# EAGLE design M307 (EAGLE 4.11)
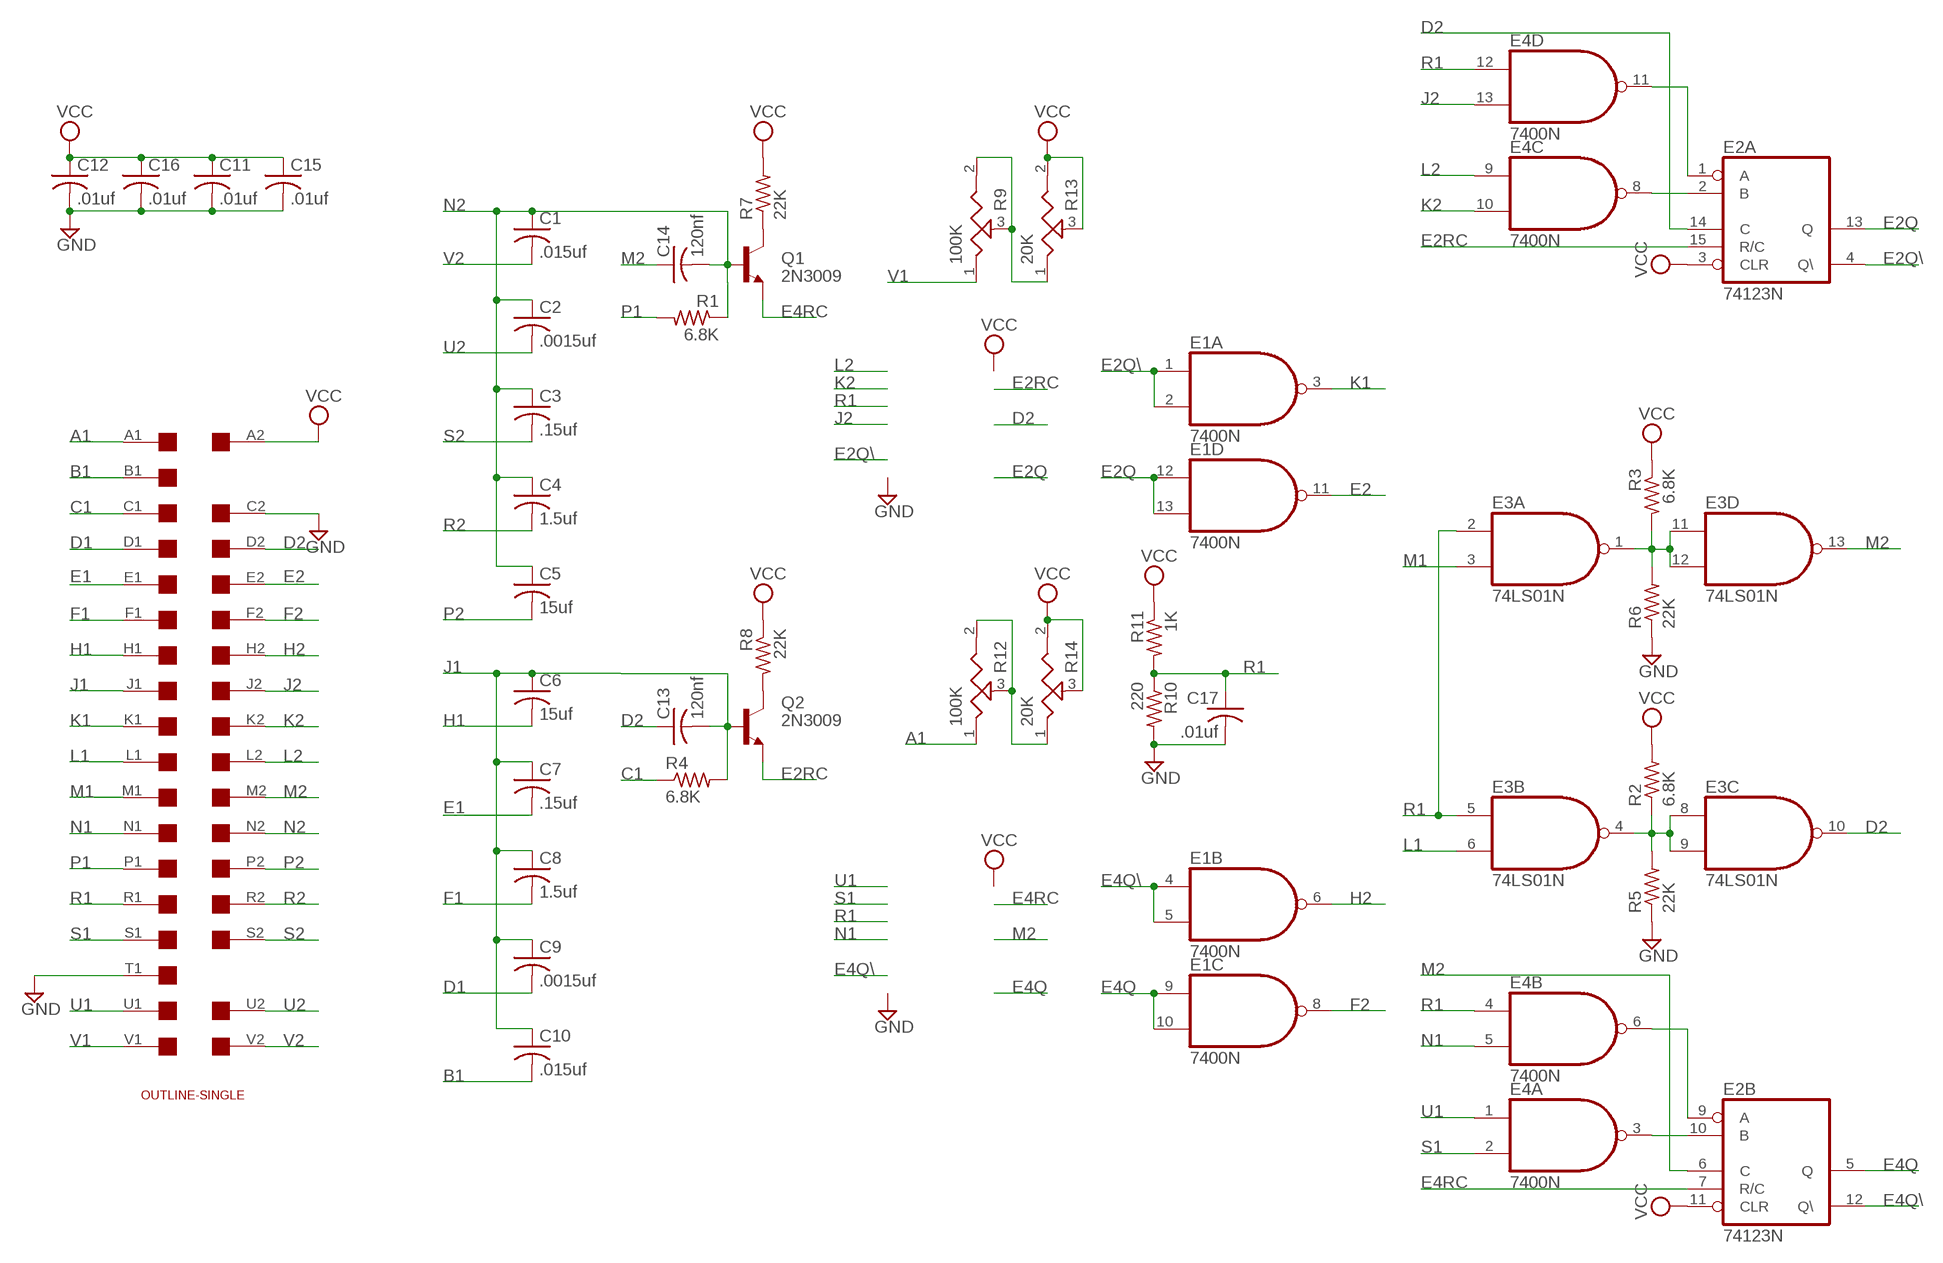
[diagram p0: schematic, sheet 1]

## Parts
C1  .015uf  C-US150-054X183  [C150-054X183]
C2  .0015uf  C-US050-025X075  [C050-025X075]
C3  .15uf  C-US102-043X133  [C102-043X133]
C4  1.5uf  C-US150-054X183  [C150-054X183]
C5  15uf  C-US150-054X183  [C150-054X183]
C6  15uf  C-US150-054X183  [C150-054X183]
C7  .15uf  C-US102-043X133  [C102-043X133]
C8  1.5uf  C-US150-054X183  [C150-054X183]
C9  .0015uf  C-US050-025X075  [C050-025X075]
C10  .015uf  C-US150-054X183  [C150-054X183]
C11  .01uf  C-US050-025X075  [C050-025X075]
C12  .01uf  C-US050-025X075  [C050-025X075]
C13  120nf  C-US075-032X103  [C075-032X103]
C14  120nf  C-US075-032X103  [C075-032X103]
C15  .01uf  C-US050-025X075  [C050-025X075]
C16  .01uf  C-US050-025X075  [C050-025X075]
C17  .01uf  C-US050-025X075  [C050-025X075]
E1  7400N  [DIL14]
E2  74123N  [DIL16]
E3  74LS01N  [DIL14]
E4  7400N  [DIL14]
Q1  2N3009  2N3019-NPN-TO39-EBC  [TO39]
Q2  2N3009  2N3019-NPN-TO39-EBC  [TO39]
R1  6.8K  R-US_0207/10  [0207/10]
R2  6.8K  R-US_0207/10  [0207/10]
R3  6.8K  R-US_0207/10  [0207/10]
R4  6.8K  R-US_0207/10  [0207/10]
R5  22K  R-US_0207/10  [0207/10]
R6  22K  R-US_0207/10  [0207/10]
R7  22K  R-US_0207/10  [0207/10]
R8  22K  R-US_0207/10  [0207/10]
R9  100K  POTUS-TRIM  [PT-SPIN]
R10  220  R-US_0207/10  [0207/10]
R11  1K  R-US_0207/10  [0207/10]
R12  100K  POTUS-TRIM  [PT-SPIN]
R13  20K  POTUS-TRIM  [PT-SPIN]
R14  20K  POTUS-TRIM  [PT-SPIN]
U$1  SINGLE  [EDGE-CON2]
U$4  OUTLINE-SINGLE  [SINGLE]

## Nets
A1: R12.1 U$1.A1
B1: C10.2 U$1.B1
C1: R4.1 U$1.C1
D1: C9.2 U$1.D1
D2: C13.1 E2.14(A:C) E3.10(C:O) U$1.D2
E1: C7.2 U$1.E1
E2: E1.11(D:O) U$1.E2
E2Q: E1.12(D:I0) E1.13(D:I1) E2.13(A:Q)
E2Q\: E1.1(A:I0) E1.2(A:I1) E2.4(A:Q\)
E2RC: E2.15(A:R/C) Q2.1(E)
E4Q: E1.9(C:I0) E1.10(C:I1) E2.5(B:Q)
E4Q\: E1.4(B:I0) E1.5(B:I1) E2.12(B:Q\)
E4RC: E2.7(B:R/C) Q1.1(E)
F1: C8.2 U$1.F1
F2: E1.8(C:O) U$1.F2
GND [power]: C11.2 C12.2 C15.2 C16.2 C17.2 R5.1 R6.1 R10.2 U$1.C2 U$1.T1
H1: C6.2 U$1.H1
H2: E1.6(B:O) U$1.H2
J1: C6.1 C7.1 C8.1 C9.1 C10.1 C13.2 Q2.2(B) R4.2 U$1.J1
J2: E4.13(D:I1) U$1.J2
K1: E1.3(A:O) U$1.K1
K2: E4.10(C:I1) U$1.K2
L1: E3.6(B:I1) U$1.L1
L2: E4.9(C:I0) U$1.L2
M1: E3.3(A:I1) U$1.M1
M2: C14.1 E2.6(B:C) E3.13(D:O) U$1.M2
N1: E4.5(B:I1) U$1.N1
N2: C1.1 C2.1 C3.1 C4.1 C5.1 C14.2 Q1.2(B) R1.1 U$1.N2
N$1: Q1.3(C) R7.1
N$2: E3.4(B:O) E3.8(C:I0) E3.9(C:I1) R2.1 R5.2
N$3: Q2.3(C) R8.2
N$4: E2.10(B:B) E4.3(A:O)
N$5: E3.1(A:O) E3.11(D:I0) E3.12(D:I1) R3.2 R6.2
N$6: E2.9(B:A) E4.6(B:O)
N$7: E2.1(A:A) E4.11(D:O)
N$8: E2.2(A:B) E4.8(C:O)
N$9 [power]: R9.2 R9.3 R13.1
N$10 [power]: R12.2 R12.3 R14.1
P1: R1.2 U$1.P1
P2: C5.2 U$1.P2
R1: C17.1 E3.2(A:I0) E3.5(B:I0) E4.4(B:I0) E4.12(D:I0) R10.1 R11.2 U$1.R1
R2: C4.2 U$1.R2
S1: E4.2(A:I1) U$1.S1
S2: C3.2 U$1.S2
U1: E4.1(A:I0) U$1.U1
U2: C2.2 U$1.U2
V1: R9.1 U$1.V1
V2: C1.2 U$1.V2
VCC [power]: C11.1 C12.1 C15.1 C16.1 E2.3(A:CLR) E2.11(B:CLR) R2.2 R3.1 R7.2 R8.1 R11.1 R13.2 R13.3 R14.2 R14.3 U$1.A2
Unconnected: U$1.B2 U$1.T2

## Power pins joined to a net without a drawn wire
GND: E1.7(P:GND) E2.8(P:GND) E3.7(P:GND) E4.7(P:GND)
VCC: E1.14(P:VCC) E2.16(P:VCC) E3.14(P:VCC) E4.14(P:VCC)

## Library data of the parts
C1-C17 = rcl:C-US: CAPACITOR, American symbol
E1 E4 = 74xx-us:74*00: Quad 2-input NAND gate
E2 = 74xx-us:74*123: Retriggerable monostable MULTIVIBRATOR
E3 = 74xx-us:74*01: Quad 2-input NAND gate, open collector
Q1 Q2 = transistor:*-NPN-: NPN Transistror
R1-R8 R10 R11 = rcl:R-US_: RESISTOR, American symbol
R9 R12-R14 = discrete:POTUS-TRIM
U$1 = dec-con:SINGLE: Single-Height DEC board
U$4 = dec-con:OUTLINE-*: Board outlines for DEC boards.

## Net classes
1 power: width 0.508 mm, drill 0.508 mm

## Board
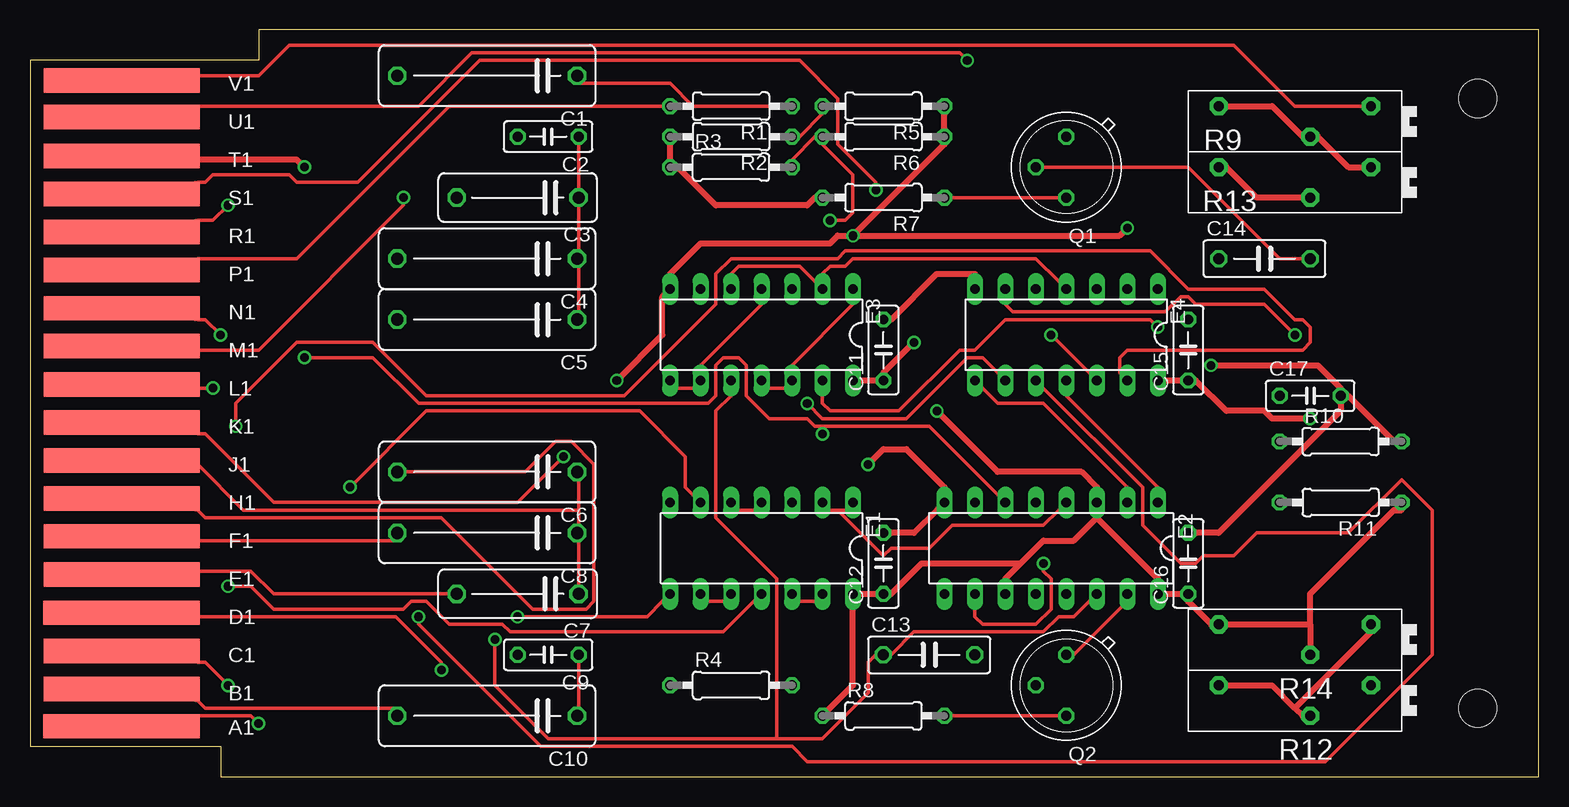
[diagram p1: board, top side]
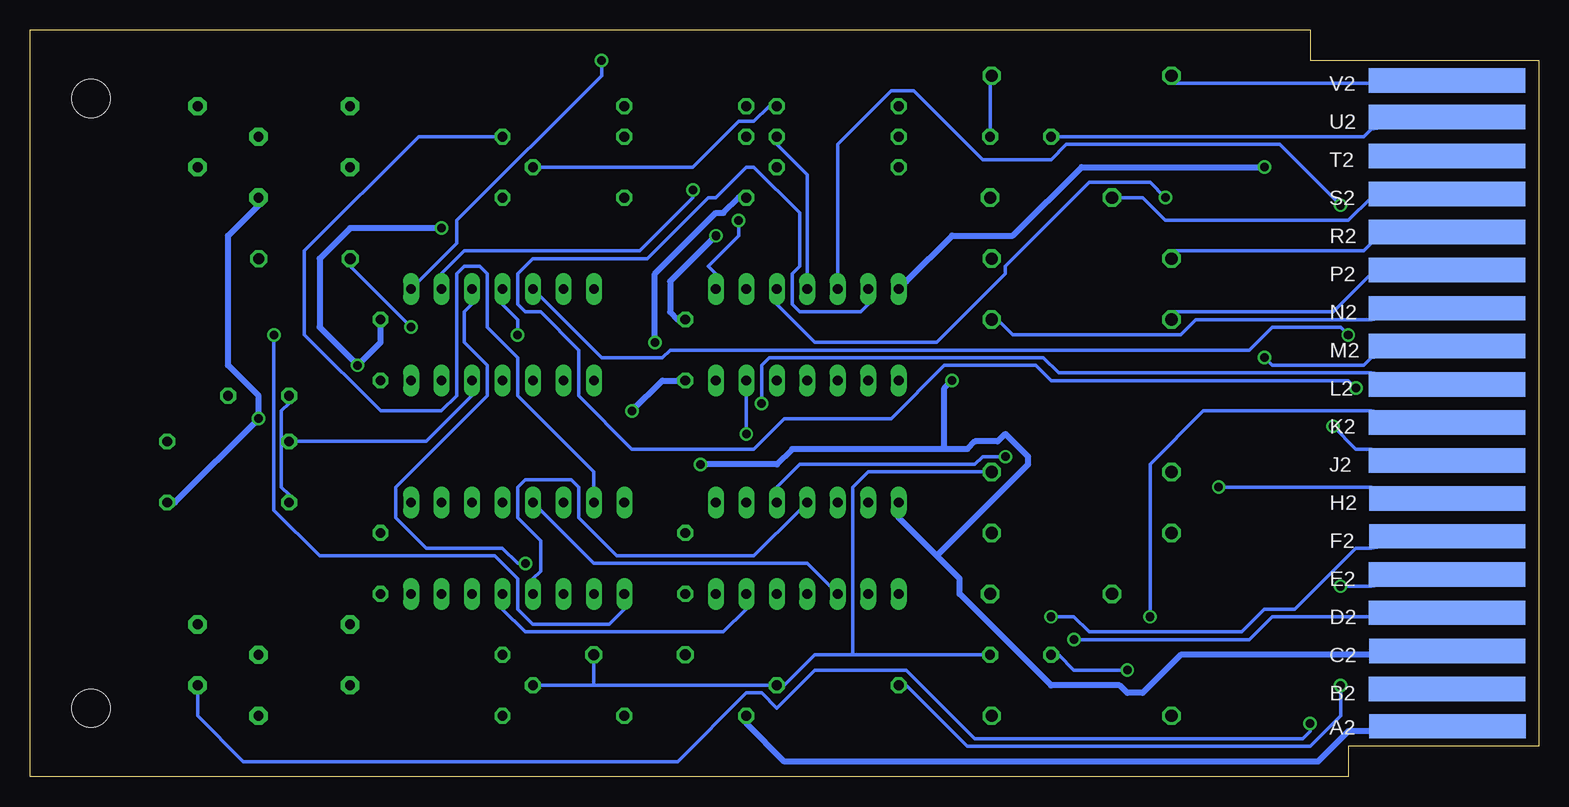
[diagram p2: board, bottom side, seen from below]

Size 125.73 x 62.23 mm. Coordinates in mm from the lower left corner, seen from the top.
Copper layers (1*16): Top 0.035mm / dielectric 1.5mm / Bottom 0.035mm
Design rules "10mils": minimum track width 12mil, minimum drill 28mil, track to track 10mil, track to pad 10mil, pad to pad 10mil, via to via 10mil, smd to smd 10mil, copper to edge 25mil, drill to drill 10mil, minimum pad ring 10mil, minimum via ring 8mil, stop-mask expansion 0mil, vias tented up to drill 0mil, thermal gap 10mil

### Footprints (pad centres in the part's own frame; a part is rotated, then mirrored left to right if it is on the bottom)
C150-054X183 = drill 1.016 octagon: 1 -7.493,0; 2 7.493,0
C050-025X075 = drill 0.813 octagon: 1 -2.54,0; 2 2.54,0
C102-043X133 = drill 1.016 octagon: 1 -5.08,0; 2 5.08,0
C075-032X103 = drill 0.914 octagon: 1 -3.81,0; 2 3.81,0
DIL14 = drill 0.813 long: 1 -7.62,-3.81; 2 -5.08,-3.81; 3 -2.54,-3.81; 4 0,-3.81; 5 2.54,-3.81; 6 5.08,-3.81; 7 7.62,-3.81; 8 7.62,3.81; 9 5.08,3.81; 10 2.54,3.81; 11 0,3.81; 12 -2.54,3.81; 13 -5.08,3.81; 14 -7.62,3.81
DIL16 = drill 0.813 long: 1 -8.89,-3.81; 2 -6.35,-3.81; 3 -3.81,-3.81; 4 -1.27,-3.81; 5 1.27,-3.81; 6 3.81,-3.81; 7 6.35,-3.81; 8 8.89,-3.81; 9 8.89,3.81; 10 6.35,3.81; 11 3.81,3.81; 12 1.27,3.81; 13 -1.27,3.81; 14 -3.81,3.81; 15 -6.35,3.81; 16 -8.89,3.81
TO39 = drill 0.813 octagon: 1 0,-2.54; 2 2.54,0; 3 0,2.54
0207/10 = drill 0.813 octagon: 1 -5.08,0; 2 5.08,0
PT-SPIN = drill 0.813 pad 1.524 octagon: 1 -6.35,-1.27; 2 6.35,-1.27; 3 -1.27,1.27
EDGE-CON2 = smd 13.017 x 2.032: A1 7.633,4.207; B1 7.639,7.327; C1 7.636,10.489; D1 7.633,13.665; E1 7.642,16.84; F1 7.642,20.041; H1 7.642,23.19; J1 7.642,26.34; K1 7.642,29.515; L1 7.642,32.69; M1 7.642,35.89; N1 7.642,39.04; P1 7.642,42.24; R1 7.642,45.39; S1 7.642,48.565; T1 7.642,51.74; U1 7.642,54.966; V1 7.642,58.026 | smd 13.017 x 2.032 bottom: A2 7.614,4.207; B2 7.642,7.328; C2 7.617,10.49; D2 7.642,13.665; E2 7.642,16.84; F2 7.617,20.041; H2 7.617,23.19; J2 7.642,26.34; K2 7.642,29.515; L2 7.642,32.69; M2 7.642,35.89; N2 7.642,39.04; P2 7.642,42.24; R2 7.642,45.39; S2 7.642,48.565; T2 7.642,51.74; U2 7.642,54.966; V2 7.642,58.026
SINGLE = hole 3.175: 120.65,56.515; 120.65,5.715

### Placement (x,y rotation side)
C1  38.1,58.42 180 top
C2  43.18,53.34 180 top
C3  40.64,48.26 180 top
C4  38.1,43.18 180 top
C5  38.1,38.1 180 top
C6  38.1,25.4 180 top
C7  40.64,15.24 180 top
C8  38.1,20.32 180 top
C9  43.18,10.16 180 top
C10  38.1,5.08 180 top
C11  71.12,35.56 90 top
C12  71.12,17.78 90 top
C13  74.93,10.16 0 top
C14  102.87,43.18 0 top
C15  96.52,35.56 90 top
C16  96.52,17.78 90 top
C17  106.68,31.75 0 top
E1  60.96,19.05 180 top
E2  85.09,19.05 180 top
E3  60.96,36.83 180 top
E4  86.36,36.83 180 top
Q1  86.36,50.8 180 top
Q2  86.36,7.62 180 top
R1  58.42,55.88 180 top
R2  58.42,53.34 180 top
R3  58.42,50.8 0 top
R4  58.42,7.62 0 top
R5  71.12,55.88 180 top
R6  71.12,53.34 180 top
R7  71.12,48.26 180 top
R8  71.12,5.08 0 top
R9  105.41,54.61 180 top
R10  109.22,27.94 0 top
R11  109.22,22.86 180 top
R12  105.41,6.35 180 top
R13  105.41,49.53 180 top
R14  105.41,11.43 180 top
U$1  0,0 0 top
U$4  0,0 0 top

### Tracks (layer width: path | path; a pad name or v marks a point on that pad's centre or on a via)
A1  (via drill 0.71)
  Top 0.305: v19.05,4.45 18.42,5.08 13.97,5.08 U$1.A1
  Bottom 0.305: v19.05,4.45 19.05,3.81 19.69,3.17 46.99,3.17 52.71,8.89 60.33,8.89 63.5,5.71 64.77,6.99 66.04,6.99 71.76,1.27 107.95,1.27 111.76,5.08 111.76,6.99 R12.1
B1
  Top 0.305: C10.2 30.48,5.71 14.61,5.71 13.97,6.35 U$1.B1
C1  (via drill 0.71)
  Top 0.305: v16.51,7.62 14.61,9.53 13.97,9.53 U$1.C1
  Bottom 0.305: v16.51,7.62 16.51,5.08 19.05,2.54 47.63,2.54 52.71,7.62 R4.1
D1  (via drill 0.71)
  Top 0.305: v34.29,8.89 34.29,9.53 30.48,13.34 13.97,13.34 U$1.D1
  Bottom 0.305: v34.29,8.89 38.74,8.89 40.01,10.16 C9.2
D2  (via drill 0.71)
  Top 0.305: v38.74,11.43 38.74,7.62 43.18,3.17 62.23,3.17 | 62.23,3.17 66.04,3.17 69.85,6.99 69.85,9.53 70.49,10.16 C13.1 71.76,10.16 73.66,12.06 84.46,12.06 85.73,13.34 87,13.34 88.27,14.61 E2.14 | 62.23,3.17 62.23,16.51 57.15,21.59 57.15,30.48 58.42,31.75 E3.10
  Bottom 0.305: v38.74,11.43 24.13,11.43 22.23,13.34 13.97,13.34 U$1.D2
E1
  Top 0.305: C7.2 34.93,15.24 20.32,15.24 18.42,17.14 13.97,17.14 U$1.E1
E2  (via drill 0.71)
  Top 0.305: v16.51,15.88 18.42,15.88 20.32,13.97 31.12,13.97 31.75,14.61 33.02,14.61 34.93,12.7 39.37,12.7 40.01,12.06 57.79,12.06 60.33,14.61 E1.11
  Bottom 0.305: v16.51,15.88 13.97,15.88 U$1.E2
E2Q
  Top 0.305: E1.12 64.14,14.61 65.41,14.61 E1.13
  Bottom 0.305: E2.13 86.36,13.97 84.46,12.06 67.95,12.06 66.04,13.97 E1.13
E2Q\
  Top 0.305: 67.31,22.23 67.95,22.23 E1.1 | 67.31,22.23 66.68,22.23 E1.2 | 67.31,22.23 71.12,18.41 71.76,19.05 74.93,19.05 76.84,20.95 84.46,20.95 85.73,22.23 E2.4
E2RC
  Top 0.305: Q2.1 87,10.16 91.44,14.61 E2.15
E4Q
  Top 0.305: E1.9 56.52,14.61 57.79,14.61 E1.10
  Bottom 0.305: E2.5 83.19,22.23 78.74,17.78 60.96,17.78 59.06,15.88 E1.10
E4Q\
  Top 0.305: E1.5 59.06,22.23 60.33,22.23 E1.4
  Bottom 0.305: E2.12 83.82,16.51 83.19,17.14 83.19,19.68 85.09,21.59 85.09,24.13 84.46,24.77 80.65,24.77 80.01,24.13 80.01,21.59 76.84,18.41 65.41,18.41 61.6,22.23 E1.4
E4RC
  Bottom 0.305: E2.7 78.74,24.13 78.74,25.4 85.09,31.75 85.09,34.92 87.63,37.47 87.63,41.91 88.27,42.55 89.54,42.55 90.17,41.91 90.17,31.75 91.44,30.48 96.52,30.48 102.87,36.83 102.87,43.81 93.35,53.34 87,53.34 Q1.1
F1
  Top 0.305: C8.2 30.48,19.68 13.97,19.68 U$1.F1
F2  (via drill 0.71)
  Top 0.305: v40.64,13.34 51.44,13.34 52.71,14.61 E1.8
  Bottom 0.305: v40.64,13.34 38.74,13.34 37.47,12.06 24.77,12.06 22.86,13.97 20.32,13.97 15.24,19.05 13.97,19.05 U$1.F2
GND  (via drill 0.71)
  Top 0.508: C12.2 71.76,20.32 73.66,20.32 75.57,22.23 E2.8 76.2,24.13 73.03,27.3 71.12,27.3 v69.85,26.04 | C16.2 97.16,20.32 99.06,20.32 109.22,30.48 109.22,31.11 C17.2 | v98.43,34.29 107.32,34.29 109.22,32.38 C17.2 | R10.2 113.67,27.94 109.86,31.75 C17.2 | R5.1 76.2,55.24 76.2,53.98 R6.1 76.2,52.7 v68.58,45.09 | C11.2 71.76,38.1 75.57,41.91 78.74,41.91 E4.7 | v22.86,50.8 22.23,51.44 13.97,51.44 U$1.T1 | v68.58,45.09 67.31,45.09 66.68,44.45 55.88,44.45 53.34,41.91 E3.7 52.71,40.01 52.71,36.83 v48.9,33.02 | v91.44,45.72 90.81,45.09 v68.58,45.09
  Bottom 0.508: 50.17,18.41 48.26,16.51 48.26,15.24 40.64,7.62 34.93,7.62 34.29,6.99 33.02,6.99 29.85,10.16 13.97,10.16 U$1.C2 | 50.17,18.41 53.34,21.59 E1.7 | v69.85,26.04 63.5,26.04 62.23,27.3 49.53,27.3 | 49.53,27.3 47.63,27.3 46.99,27.94 45.09,27.94 44.45,28.57 42.55,26.67 42.55,26.04 50.17,18.41 | C15.2 96.52,37.47 96.52,36.2 v98.43,34.29 101.6,37.47 101.6,43.18 99.06,45.72 v91.44,45.72 | v68.58,45.09 72.39,41.27 72.39,38.73 71.76,38.1 C11.2 | v22.86,50.8 38.1,50.8 43.82,45.09 48.9,45.09 52.71,41.27 E3.7 | 49.53,27.3 49.53,32.38 v48.9,33.02
H1
  Top 0.305: C6.2 31.12,25.4 41.28,25.4 43.82,27.94 45.09,27.94 46.99,26.04 46.99,14.61 46.36,13.97 41.91,13.97 34.29,21.59 14.61,21.59 13.97,22.23 U$1.H1
H2  (via drill 0.71)
  Top 0.305: v26.67,24.13 33.02,30.48 50.8,30.48 54.61,26.67 54.61,24.13 55.25,23.5 E1.6
  Bottom 0.305: v26.67,24.13 13.97,24.13 U$1.H2
J1
  Top 0.305: C9.1 45.72,9.53 45.72,5.71 C10.1 | C7.1 45.72,15.88 45.72,19.68 C8.1 45.72,20.95 45.72,22.23 | 45.72,22.23 45.72,24.77 C6.1 | 45.72,22.23 17.78,22.23 13.97,26.04 U$1.J1
  Bottom 0.305: 78.74,7.62 83.19,7.62 Q2.2 | 78.74,7.62 64.14,7.62 R4.2 62.87,7.62 60.33,10.16 57.15,10.16 | 78.74,7.62 78.74,9.53 C13.2 | 57.15,10.16 46.36,10.16 C9.1 | 57.15,10.16 57.15,24.13 55.88,25.4 45.72,25.4 C6.1
J2  (via drill 0.71)
  Top 0.305: v17.15,29.21 17.15,31.11 22.23,36.2 28.58,36.2 33.02,31.75 49.53,31.75 57.15,39.37 57.15,41.91 58.42,43.18 67.31,43.18 67.95,43.81 93.35,43.81 96.52,40.64 102.87,40.64 105.41,38.1 106.05,38.1 106.68,37.47 106.68,36.2 106.05,35.56 91.44,35.56 90.81,34.92 90.81,33.66 E4.13
  Bottom 0.305: v17.15,29.21 15.24,27.3 13.97,27.3 U$1.J2
K1  (via drill 0.71)
  Top 0.305: v44.45,26.67 40.64,22.86 20.32,22.86 14.61,28.57 13.97,28.57 U$1.K1
  Bottom 0.305: v44.45,26.67 46.36,26.67 46.99,26.04 61.6,26.04 63.5,24.13 E1.3
K2  (via drill 0.71)
  Top 0.305: v32.39,13.34 32.39,12.7 42.55,2.54 63.5,2.54 64.77,1.27 107.95,1.27 116.84,10.16 116.84,22.23 114.3,24.77 109.86,20.32 102.24,20.32 100.33,18.41 97.79,18.41 97.16,17.78 95.89,17.78 92.71,20.95 92.71,24.13 84.46,32.38 E4.10
  Bottom 0.305: v32.39,13.34 32.39,26.04 27.94,30.48 13.97,30.48 U$1.K2
L1  (via drill 0.71)
  Top 0.305: v15.24,32.38 13.97,32.38 U$1.L1
  Bottom 0.305: v15.24,32.38 15.88,33.02 40.64,33.02 41.91,34.29 49.53,34.29 53.98,29.84 62.87,29.84 65.41,27.3 75.57,27.3 80.01,31.75 80.01,35.56 83.19,38.73 84.46,38.73 85.09,39.37 85.09,41.91 83.82,43.18 74.3,43.18 69.22,48.26 68.58,48.26 66.04,50.8 65.41,50.8 61.6,46.99 61.6,42.55 62.23,41.91 62.23,39.37 61.6,38.73 56.52,38.73 55.88,39.37 E3.6
L2  (via drill 0.71)
  Top 0.305: v64.77,31.11 66.04,29.84 73.03,29.84 78.11,34.92 79.38,34.92 80.65,33.66 E4.9
  Bottom 0.305: v64.77,31.11 64.77,34.29 64.14,34.92 41.28,34.92 40.01,33.66 13.97,33.66 U$1.L2
M1  (via drill 0.71)
  Top 0.305: v31.12,48.26 31.12,47.62 19.05,35.56 13.97,35.56 U$1.M1
  Bottom 0.305: v31.12,48.26 32.39,49.53 37.47,49.53 44.45,42.55 44.45,41.91 50.17,36.2 60.33,36.2 63.5,39.37 E3.3
M2  (via drill 0.71)
  Top 0.305: v22.86,34.92 28.58,34.92 32.39,31.11 56.52,31.11 57.15,31.75 57.15,34.29 57.79,34.92 59.06,34.92 59.69,34.29 59.69,31.75 61.6,29.84 64.77,29.84 65.41,29.21 66.04,29.21 | 66.04,29.21 74.93,29.21 80.65,23.5 E2.6 | 66.04,29.21 v66.04,28.57 | v93.98,37.47 93.35,38.1 81.28,38.1 78.74,35.56 77.47,35.56 72.39,30.48 66.68,30.48 66.04,31.11 66.04,31.75 E3.13
  Bottom 0.305: v22.86,34.92 22.23,34.29 14.61,34.29 13.97,34.92 U$1.M2 | v66.04,28.57 66.04,31.75 E3.13 | v93.98,37.47 99.06,42.55 C14.1
N1  (via drill 0.71)
  Top 0.305: v15.88,36.83 14.61,38.1 13.97,38.1 U$1.N1
  Bottom 0.305: v15.88,36.83 16.51,37.47 22.23,37.47 24.13,35.56 72.39,35.56 73.03,34.92 78.11,34.92 83.19,40.01 E4.5
N2
  Top 0.305: Q1.2 84.46,50.8 96.52,50.8 104.14,43.18 106.05,43.18 C14.2 | C5.1 45.72,38.73 45.72,42.55 C4.1 45.72,43.81 45.72,47.62 C3.1 45.72,48.9 45.72,52.7 C2.1 | R1.1 62.87,55.88 55.25,55.88 53.34,57.78 45.72,57.78 C1.1
  Bottom 0.305: C2.1 45.72,53.98 45.72,57.78 C1.1 | Q1.2 83.19,50.8 70.49,50.8 66.68,54.61 65.41,54.61 64.14,55.88 R1.1 | U$1.N2 13.97,38.1 28.58,38.1 29.85,36.83 43.82,36.83 45.09,38.1 C5.1
N$1
  Top 0.305: R7.1 76.84,48.26 85.73,48.26 Q1.3
N$2
  Top 0.305: R2.1 64.14,53.34 66.04,55.24 R5.2 | E3.8 53.98,32.38 55.25,32.38 E3.9 55.88,34.29 60.96,39.37 E3.4
  Bottom 0.305: R2.1 63.5,52.7 60.96,50.16 60.96,41.91 E3.4
N$3
  Top 0.305: R8.2 76.84,5.08 85.73,5.08 Q2.3
N$4  (via drill 0.71)
  Top 0.305: v84.46,17.78 84.46,17.14 85.09,16.51 85.09,13.97 83.82,12.7 79.38,12.7 78.74,13.34 78.74,13.97 E2.10
  Bottom 0.305: v84.46,17.78 85.09,17.78 86.36,19.05 92.71,19.05 95.25,21.59 95.25,24.13 87.63,31.75 87.63,34.29 89.54,36.2 89.54,38.73 88.9,39.37 E4.3
N$5  (via drill 0.71)
  Top 0.305: R3.2 63.5,51.44 65.41,53.34 R6.2 66.04,52.7 68.58,50.16 68.58,46.99 67.95,46.35 v66.68,46.35 | E3.11 61.6,32.38 62.87,32.38 E3.12 63.5,34.29 68.58,39.37 E3.1
  Bottom 0.305: v66.68,46.35 66.68,45.09 69.22,42.55 68.58,41.91 E3.1
N$6  (via drill 0.71)
  Top 0.305: v105.41,36.83 102.87,39.37 97.16,39.37 96.52,40.01 95.89,40.01 94.62,38.73 81.92,38.73 81.28,39.37 E4.6
  Bottom 0.305: v105.41,36.83 105.41,22.23 101.6,18.41 87,18.41 85.09,16.51 85.09,13.97 83.82,12.7 77.47,12.7 76.2,13.97 E2.9
N$7
  Top 0.305: E2.1 93.98,24.13 86.36,31.75 E4.11
N$8
  Top 0.305: E2.2 91.44,24.13 84.46,31.11 80.65,31.11 79.38,32.38 E4.8
N$9
  Top 0.508: R9.2 99.7,55.88 103.51,55.88 106.05,53.34 R9.3 107.32,53.34 109.86,50.8 111.13,50.8 R13.1
N$10
  Top 0.508: 105.41,5.71 106.05,5.08 R12.3 | 105.41,5.71 103.51,7.62 99.7,7.62 R12.2 | 105.41,5.71 111.76,12.06 R14.1
P1
  Top 0.305: R1.2 52.71,55.88 34.93,55.88 22.23,43.18 13.97,43.18 U$1.P1
P2
  Bottom 0.305: C5.2 30.48,38.73 17.15,38.73 13.97,41.91 U$1.P2
R1  (via drill 0.71)
  Top 0.305: v85.09,36.83 88.27,33.66 E4.12 | v16.51,47.62 15.24,46.35 13.97,46.35 U$1.R1 | E3.5 58.42,41.91 59.06,42.55 64.14,42.55 65.41,41.27 E3.2 66.04,41.91 66.68,42.55 67.95,42.55 68.58,43.18 83.82,43.18 85.73,41.27 E4.4
  Bottom 0.305: 104.78,27.94 104.78,24.13 104.14,23.5 R11.2 | R10.1 104.78,27.94 | 104.78,27.94 104.78,30.48 104.14,31.11 C17.1 | R10.1 104.78,27.94 | v85.09,36.83 85.09,38.1 86.36,39.37 E4.4 | R10.1 103.51,27.94 92.71,27.94 88.9,31.75 E4.12 | v16.51,47.62 21.59,52.7 39.37,52.7 40.64,51.44 46.36,51.44 52.07,57.15 53.98,57.15 58.42,52.7 58.42,41.91 E3.5
R2
  Bottom 0.305: C4.2 30.48,43.81 14.61,43.81 13.97,44.45 U$1.R2
S1  (via drill 0.71)
  Top 0.305: v70.49,48.9 70.49,49.53 67.31,52.7 67.31,56.52 64.14,59.69 37.47,59.69 27.31,49.53 22.23,49.53 21.59,50.16 15.24,50.16 14.61,49.53 13.97,49.53 U$1.S1
  Bottom 0.305: v70.49,48.9 70.49,48.26 74.93,43.81 89.54,43.81 91.44,41.91 E4.2
S2
  Bottom 0.305: C3.2 34.93,48.26 33.02,48.26 31.12,46.35 15.88,46.35 13.97,48.26 U$1.S2
U1  (via drill 0.71)
  Top 0.305: v78.11,59.69 77.47,60.33 36.83,60.33 32.39,55.88 13.97,55.88 U$1.U1
  Bottom 0.305: v78.11,59.69 78.11,58.42 90.17,46.35 90.17,44.45 93.35,41.27 E4.1
U2
  Bottom 0.305: C2.2 40.01,53.34 14.61,53.34 13.97,53.98 U$1.U2
V1
  Top 0.305: R9.1 111.13,55.88 105.41,55.88 100.33,60.96 21.59,60.96 19.05,58.42 13.97,58.42 U$1.V1
V2
  Bottom 0.305: C1.2 30.48,57.78 13.97,57.78 U$1.V2
VCC  (via drill 0.71)
  Top 0.508: R8.1 68.58,7.62 68.58,13.97 E1.14 69.22,15.24 70.49,15.24 C12.1 71.76,15.24 74.3,17.78 82.55,17.78 | E3.14 69.22,33.02 70.49,33.02 C11.1 71.12,33.66 v73.66,36.2 | R2.2 53.34,52.7 53.34,51.44 R3.1 53.98,50.8 57.15,47.62 64.77,47.62 65.41,48.26 R7.2 | 82.55,17.78 84.46,19.68 87,19.68 88.9,21.59 | 82.55,17.78 81.28,16.51 E2.11 | 88.9,21.59 E2.3 | R13.3 106.05,48.26 102.24,48.26 99.7,50.8 R13.2 | E4.14 94.62,33.02 95.89,33.02 C15.1 97.16,33.02 99.7,30.48 102.87,30.48 103.51,29.84 v106.68,29.84 | 106.68,12.7 106.68,10.79 R14.3 | 106.68,12.7 106.68,15.24 113.67,22.23 114.3,22.23 R11.1 | 106.68,12.7 99.7,12.7 R14.2 98.43,12.7 96.52,14.61 C16.1 95.89,15.24 94.62,15.24 E2.16 93.98,16.51 88.9,21.59 | 88.9,21.59 E2.3 | v75.57,30.48 80.65,25.4 87.63,25.4 88.9,24.13 E2.3
  Bottom 0.508: U$1.A2 13.97,3.81 15.88,3.81 18.42,1.27 62.87,1.27 66.04,4.45 R8.1 | v73.66,36.2 73.66,41.91 68.58,46.99 67.95,46.99 66.68,48.26 R7.2 | R11.1 113.67,22.86 v106.68,29.84 106.68,31.75 109.22,34.29 109.22,45.09 106.68,47.62 R13.3 | v75.57,30.48 73.03,33.02 71.76,33.02 C11.1

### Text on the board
tValues: Coarse | Fine | Fine | Coarse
